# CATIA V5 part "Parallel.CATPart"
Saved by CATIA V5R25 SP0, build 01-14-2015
Part number: Part1
Bounding box of the stored display mesh (mm): x 0 to 150, y -29.343 to 29.343, z 0 to 29.342
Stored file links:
  E:\cadcim\GSD_cat_v5-6r2014\Part_files\Parallel.CATPart
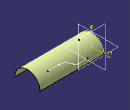
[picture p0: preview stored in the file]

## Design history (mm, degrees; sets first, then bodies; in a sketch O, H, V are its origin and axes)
Set1
  Sketch1 on yz-plane, origin (0, 0, 0), H (0, 1, 0), V (0, 0, 1)
    arc A1 centre (0, 0) radius 29.3431 from (29.3431, 0) to (-29.3431, 0) ccw
  Extrude1: Lim1 150, Lim2 0, Element1 Sketch1
  Sketch2 on zx-plane, origin (0, 0, 0), H (-1, 0, 0), V (0, 0, 1)
    line L1 (-121.5409, 21.8559) -> (-95.9964, 21.8559)
    line L2 (-59.5104, 9.3216) -> (-37.7891, 9.3216)
    arc A1 centre (-95.9964, -22.962) radius 44.8179 from (-95.9964, 21.8559) to (-68.4537, 12.394) cw
    arc A2 centre (-59.5104, 23.8743) radius 14.5527 from (-68.4537, 12.394) to (-59.5104, 9.3216) ccw
    radius A1 = 44.8179
    radius A2 = 14.5527
    horizontal: L1 H, L2 H
    tangency: A1 L1, A2 A1, A2 L2
  Extrude2: Lim1 150, Lim2 0, Element1 Sketch2
  Intersect1: ToIntersect1 Extrude2, ToIntersect2 Extrude1
Body1 (main body)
